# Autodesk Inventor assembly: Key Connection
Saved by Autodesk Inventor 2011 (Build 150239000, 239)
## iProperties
Created: 2011-05
Part Number: Key Connection
Document SubType Name: Assembly
Designer: 904Chiaki
ClientObjectVersion: 1
Author: 904Chiaki
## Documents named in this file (1)
- E:\2.FINISH\DOAN_CTM_final\Lap1_codai\Design Accelerator\Key Connection2.iam
